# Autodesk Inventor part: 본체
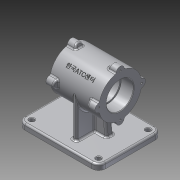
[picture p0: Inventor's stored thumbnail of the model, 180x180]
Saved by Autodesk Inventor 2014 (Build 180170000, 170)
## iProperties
Created: 2015-12
Part Number: 본체
Material: 알루미늄 6061
Document SubType Name: Modeling
Designer: test_03
Density: 2.71 g/cm^3
Appearance: 알루미늄 - 평지
Mass: 1165.19 g
Surface Area: 815.535 cm^2
Volume: 429.959 cm^3
Author: test_03
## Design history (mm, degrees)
sketch "스케치1"
  geometry: L1 (-42.5, 0)-(42.5, 0); L2 (-42.5, 23.5)-(-20.5, 23.5); L3 (-20.5, 23.5)-(-20.5, 21); L4 (-20.5, 21)-(20.5, 21); L5 (20.5, 21)-(20.5, 23.5); L6 (20.5, 23.5)-(42.5, 23.5); L7 (42.5, 23.5)-(42.5, 37); L8 (42.5, 37)-(-42.5, 37); L9 (-42.5, 37)-(-42.5, 23.5); 5 further points
  constraints: 18 end point, 6 parallel, 4 midpoint, 3 vertical alignment, 2 coincident, 1 collinear, 1 horizontal, 1 perpendicular
  dimensions: "d0" = 85 distance of L1.start L1.end; "d1" = 42 diameter of L4 L1; "d2" = 47 diameter of L6 L1; "d3" = 47 diameter of L2 L1; "d4" = 74 diameter of L8 L1; "d5" = 22 distance of L2.start L2.end
revolve "회전1" sketch "스케치1" stored, may be unused: angle "d6" = 90 deg
node "작업 평면1"
sketch "스케치3"
  geometry: L1 (-68, 55)-(48, 55); L2 (60, 43)-(60, -43); L3 (48, -55)-(-68, -55); L4 (-80, -43)-(-80, 43); C1 r 4 at (-68, 43); C2 r 4 at (48, 43); C3 r 4 at (48, -43); C4 r 4 at (-68, -43); A1 r 12 centre (-68, 43) between (-68, 55) and (-80, 43); A2 r 12 centre (-68, -43) between (-80, -43) and (-68, -55); A3 r 12 centre (48, -43) between (48, -55) and (60, -43); A4 r 12 centre (48, 43) between (60, 43) and (48, 55); 5 further points
  constraints: 8 centre point, 8 end point, 8 point on circle, 8 tangent, 6 equal radius, 6 point on line, 4 coincident, 2 parallel, 1 horizontal, 1 horizontal alignment, 1 midpoint, 1 perpendicular
  dimensions: "d11" = 110 distance of point (60, 55) point (60, -55); "d12" = 140 distance of point (-80, 55) point (60, 55); "d13" = 80 distance from line of point (0, 0) L4; "d14" = 12 radius of A1; "d15" = 8 diameter of C1
extrude "돌출2" join sketch "스케치3" distance "d16" = 10; taper "d17" = 0 deg
sketch "스케치4"
  geometry: L1 (43, -70)-(-43, -70) reference; L2 (-37, 0)-(-37, -70); L3 (37, 0)-(37, -70); A1 r 37 centre (0, 0) between (-37, 0) and (37, 0) reference; 1 further point
  constraints: 4 end point, 2 perpendicular, 2 point on circle, 2 point on line, 2 tangent
extrude "돌출3" join sketch "스케치4" stored distance "d18" = 8; taper "d19" = 0 deg
sketch "스케치5"
  geometry: L1 (-42.5, -37)-(42.5, -37) reference; L2 (-48, -70)-(68, -70) reference; L3 (-20.948, -37)-(-25, -70); L4 (20.948, -37)-(25, -70); L5 (0, 0)-(0, -70)
  constraints: 6 end point, 5 point on line, 1 perpendicular, 1 other
  dimensions: "d20" = 97 deg angle of L2 L3; "d21" = 50 distance of L3.end L4.end
feature "리브1" dims "d22" = 1, "d23" = 12, "d24" = 0, "d25" = 0, "d26" = 1, "d27" = 1
feature "리브2" dims "d28" = 1, "d29" = 12, "d30" = 0, "d31" = 0, "d32" = 1, "d33" = 1
sketch "스케치7"
  geometry: L1 (-37, 0)-(0, 0); L2 (0, 0)-(-37.194, 37.194); 1 further point
  constraints: 4 end point, 1 horizontal, 1 horizontal alignment, 1 other
  dimensions: "d34" = 45 deg angle of L1 L2
node "작업 평면2"
sketch "스케치8"
  geometry: 2 further points
  constraints: 1 coincident, 1 other
feature "엠보싱1" sketch "스케치8" dims "d35" = 0.5, "d36" = 0
sketch "스케치9"
  geometry: C1 r 23.5 at (0, 0) reference; C2 r 7 at (-37, 0); C3 r 6.24 at (0, -37); C4 r 8.855 at (0, 37); C5 r 6.29 at (37, 0); A1 r 37 centre (0, 0) between (-37, 0) and (0, -37) reference
  constraints: 4 centre point, 4 point on circle, 1 horizontal alignment
  dimensions: "d37" = 14 diameter of C2
extrude "돌출4" join sketch "스케치9" distance "d38" = 15; taper "d39" = 0 deg
fillet "모깎기1" dims "d40" = 3
fillet "모깎기2" dims "d41" = 3
fillet "모깎기3" dims "d42" = 0.3
chamfer "모따기1" distance "d43" = 1; stored, may be unused: second distance "d44" = 2, angle "d45" = 45 deg
sketch "스케치11"
  geometry: 1 further point
hole "구멍1" diameter "d51" = 3.242; stored, may be unused: countersink angle "d55" = 90 deg, drill point angle "d57" = 118 deg; dims "d49" = 10, "d50" = 10, "d52" = 9, "d53" = 4, "d54" = 2, "d56" = 11
sketch "스케치13"
  geometry: L1 (-27.5, 37)-(42.5, 37) reference; L2 (-42.5, 36.338)-(-42.5, 36.338) reference; L3 (-42.5, 44)-(-27.5, 44) reference; L4 (-27.5, 37)-(-30.048, 44); L5 (-27.5, 44)-(-27.5, 37); L6 (-27.5, 44)-(-30.048, 44); L7 (108, 0)-(-88, 0) reference; L8 (-27.5, 36.338)-(-27.5, 36.338) reference; L9 (-27.5, 36.338)-(-42.5, 36.338) reference; L10 (-42.5, 36.338)-(-27.5, 36.338) reference; 1 further point
  constraints: 6 end point, 1 perpendicular, 1 point on line
  dimensions: "d63" = 110 deg angle of L1 L4
revolve "회전2" sketch "스케치13" stored, may be unused: angle "d64" = 90 deg
sketch "스케치14"
  geometry: L1 (27.5, 44)-(42.5, 44) reference; L2 (-27.5, 37)-(27.5, 37) reference; L3 (27.5, 37)-(30.048, 44); L4 (27.5, 37)-(27.5, 44); L5 (27.5, 44)-(30.048, 44); L6 (108, 0)-(-88, 0) reference; 1 further point
  constraints: 6 end point, 2 perpendicular, 1 point on line
  dimensions: "d65" = 110 deg angle of L2 L3
revolve "회전3" sketch "스케치14" stored, may be unused: angle "d66" = 90 deg
fillet "모깎기11" dims "d72" = 3
fillet "모깎기12" dims "d73" = 3
node "솔리드1"
pattern_circular "원형 패턴1" dims angle "d59" = 360 deg
mirror "대칭1"
node "투영된 루프1"
